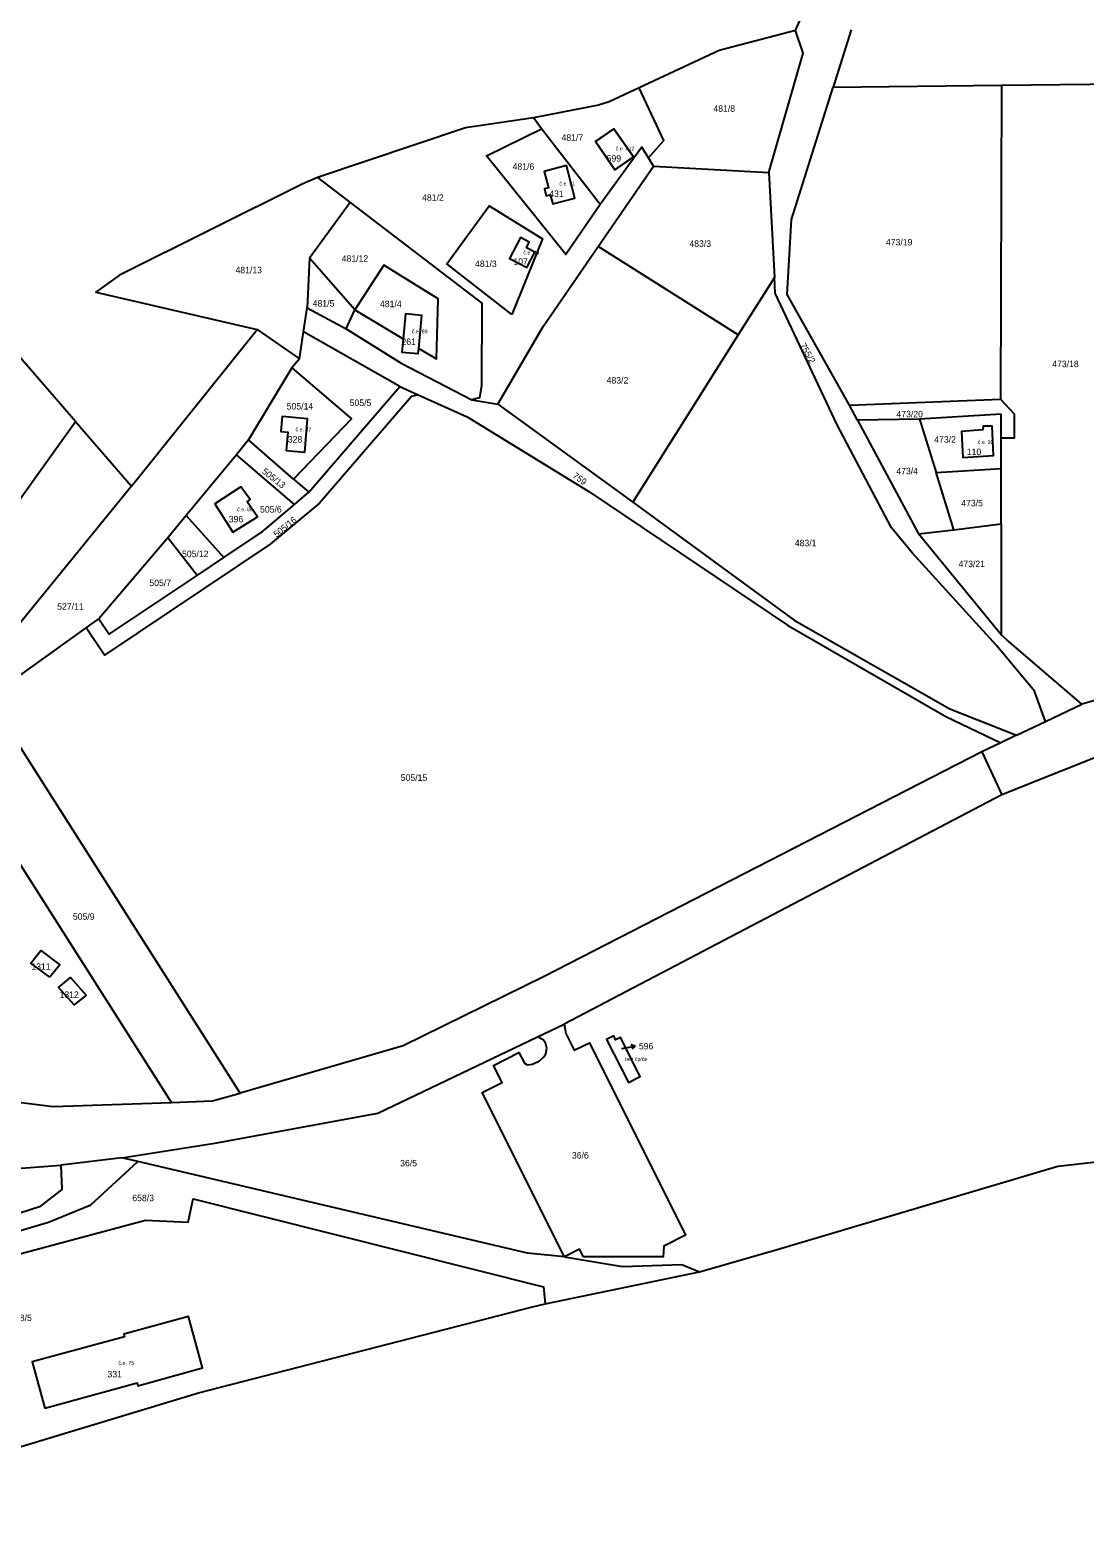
# Model space of a CAD drawing. Extents: x -887272 to -877616, y -1026687 to -1019819.
# Drawn here: x -883645.6 to -883368.4, y -1024159.5 to -1023763.3 of the extents above; entities that cross this region are included whole.
import ezdxf

# ---------------------------------------------------------------- set-up
doc = ezdxf.new("R2010")
doc.units = 0
for name, color, linetype in [('Definiční body', 7, 'Continuous'), ('Hranice parcel', 7, 'Continuous'), ('Parcelní čísla', 7, 'Continuous'), ('Polygon budovy', 7, 'Continuous'), ('Pop  PČ popisy', 7, 'Continuous')]:
    doc.layers.add(name, color=color, linetype=linetype)

msp = doc.modelspace()

# ---------------------------------------------------------------- linework, layer by layer
at = {"layer": 'Hranice parcel'}
for p, q in [((-883633.66, -1023866.14), (-883788.3, -1023688.23)), ((-883444.46, -1023763.44), (-883427.95, -1023725.46)), ((-883429.84, -1023763.22), (-883434.55, -1023778.27)), ((-883434.55, -1023778.27), (-883390.32, -1023777.79)), ((-883390.32, -1023777.79), (-883390.61, -1023860.31)), ((-883390.32, -1023777.79), (-883353.3, -1023777.4)), ((-883511.21, -1023789.27), (-883513.28, -1023786.33)), ((-883495.74, -1023809.17), (-883511.21, -1023789.27)), ((-883481.76, -1023799.1), (-883483.12, -1023796.92)), ((-883570.02, -1023802.03), (-883561.45, -1023808.59)), ((-883496.31, -1023820.22), (-883481.76, -1023799.1)), ((-883481.76, -1023799.1), (-883451.46, -1023800.74)), ((-883451.46, -1023800.74), (-883450.01, -1023828.34)), ((-883561.45, -1023808.59), (-883572.14, -1023823.24)), ((-883459.48, -1023843.4), (-883496.31, -1023820.22)), ((-883572.14, -1023823.24), (-883572.76, -1023836.34)), ((-883450.01, -1023828.34), (-883459.48, -1023843.4)), ((-883573.72, -1023842.6), (-883572.76, -1023836.34)), ((-883572.76, -1023836.34), (-883562.48, -1023841.78)), ((-883546.95, -1023837.89), (-883547.55, -1023844.48)), ((-883618.89, -1023883.14), (-883585.89, -1023842)), ((-883585.89, -1023842), (-883574.82, -1023849.7)), ((-883574.82, -1023849.7), (-883573.72, -1023842.6)), ((-883548.42, -1023856.97), (-883573.72, -1023842.6)), ((-883547.55, -1023844.48), (-883547.87, -1023847.97)), ((-883459.48, -1023843.4), (-883487.2, -1023887.41)), ((-883574.82, -1023849.7), (-883576.78, -1023852.03)), ((-883576.78, -1023852.03), (-883588.17, -1023871.03)), ((-883572.33, -1023884.75), (-883548.42, -1023856.97)), ((-883548.42, -1023856.97), (-883543.56, -1023859.14)), ((-883529.54, -1023860.45), (-883522.66, -1023861.64)), ((-883522.66, -1023861.64), (-883487.2, -1023887.41)), ((-883430.28, -1023861.87), (-883390.61, -1023860.31)), ((-883428.2, -1023865.83), (-883430.28, -1023861.87)), ((-883411.84, -1023865.52), (-883428.2, -1023865.83)), ((-883428.2, -1023865.83), (-883412.13, -1023895.71)), ((-883390.38, -1023864.26), (-883411.84, -1023865.52)), ((-883411.84, -1023865.52), (-883407.49, -1023879.6)), ((-883390.39, -1023870.51), (-883390.38, -1023864.26)), ((-883633.66, -1023866.14), (-883618.89, -1023883.14)), ((-883588.17, -1023871.03), (-883591.35, -1023874.89)), ((-883576.32, -1023881.3), (-883588.17, -1023871.03)), ((-883390.4, -1023878.54), (-883390.39, -1023870.51)), ((-883591.35, -1023874.89), (-883604.52, -1023890.86)), ((-883576.14, -1023887.99), (-883591.35, -1023874.89)), ((-883576.32, -1023881.3), (-883572.33, -1023884.75)), ((-883407.49, -1023879.6), (-883390.4, -1023878.54)), ((-883402.86, -1023894.6), (-883407.49, -1023879.6)), ((-883390.42, -1023893.04), (-883390.4, -1023878.54)), ((-883618.89, -1023883.14), (-883653, -1023925)), ((-883576.14, -1023887.99), (-883572.33, -1023884.75)), ((-883604.52, -1023890.86), (-883609.36, -1023896.72)), ((-883604.52, -1023890.86), (-883594.64, -1023901.88)), ((-883402.86, -1023894.6), (-883390.42, -1023893.04)), ((-883390.42, -1023893.04), (-883390.4, -1023922.22)), ((-883609.36, -1023896.72), (-883627.54, -1023918.05)), ((-883601.71, -1023906.6), (-883609.36, -1023896.72)), ((-883412.13, -1023895.71), (-883402.86, -1023894.6)), ((-883390.4, -1023922.22), (-883412.13, -1023895.71)), ((-883601.71, -1023906.6), (-883594.64, -1023901.88)), ((-883656.45, -1023938.75), (-883630.8, -1023920.38)), ((-883630.8, -1023920.38), (-883627.54, -1023918.05)), ((-883353.44, -1023936), (-883369.18, -1023940.44)), ((-883590.41, -1024042.65), (-883656.45, -1023938.75)), ((-883378.78, -1023945.02), (-883369.18, -1023940.44)), ((-883386.38, -1023948.64), (-883378.78, -1023945.02)), ((-883608.39, -1024045.1), (-883669.93, -1023948.4)), ((-883386.38, -1023948.64), (-883390.5, -1023950.62)), ((-883390.5, -1023950.62), (-883395.52, -1023952.98)), ((-883395.52, -1023952.98), (-883390.28, -1023964.24)), ((-883390.28, -1023964.24), (-883505.22, -1024024.55)), ((-883512.22, -1024027.85), (-883505.22, -1024024.55)), ((-883621.46, -1024059.64), (-883637.46, -1024061.6)), ((-883617.24, -1024060.68), (-883621.46, -1024059.64)), ((-883510.26, -1024098.08), (-883469.7, -1024089.6))]:
    msp.add_line(p, q, dxfattribs=at)
for points in [[(-883444.46, -1023763.44), (-883464.53, -1023768.66), (-883485.56, -1023778.53)], [(-883451.46, -1023800.74), (-883442.46, -1023769.38), (-883444.46, -1023763.44)], [(-883485.56, -1023778.53), (-883493.38, -1023782.2), (-883496.2, -1023783), (-883513.28, -1023786.33)], [(-883483.12, -1023796.92), (-883479.07, -1023792.34), (-883485.56, -1023778.53)], [(-883430.28, -1023861.87), (-883446.66, -1023832.78), (-883445.52, -1023813.08), (-883434.55, -1023778.27)], [(-883513.28, -1023786.33), (-883531.14, -1023788.98), (-883570.02, -1023802.03)], [(-883495.74, -1023809.17), (-883504.77, -1023822.27), (-883525.68, -1023796.36), (-883511.21, -1023789.27)], [(-883491.94, -1023800.04), (-883496.99, -1023792.63), (-883492.23, -1023789.26), (-883487.02, -1023796.59), (-883491.94, -1023800.04)], [(-883483.12, -1023796.92), (-883484.87, -1023794.12), (-883495.74, -1023809.17)], [(-883570.02, -1023802.03), (-883574.04, -1023803.84), (-883622.1, -1023827.7), (-883628.32, -1023832.18), (-883585.89, -1023842)], [(-883508.25, -1023808.95), (-883502.45, -1023807.49), (-883504.6, -1023798.93), (-883510.53, -1023800.47), (-883509.38, -1023804.74), (-883510.44, -1023805.02), (-883509.95, -1023806.87), (-883508.89, -1023806.58), (-883508.25, -1023808.95)], [(-883561.45, -1023808.59), (-883526.89, -1023835.05), (-883526.96, -1023856.69), (-883527.52, -1023859.93), (-883529.54, -1023860.45)], [(-883519.02, -1023838.04), (-883536.1, -1023824.78), (-883524.92, -1023809.52), (-883510.92, -1023818.14), (-883519.02, -1023838.04)], [(-883515.02, -1023825.7), (-883512.96, -1023821.7), (-883515.18, -1023820.56), (-883514.4, -1023819.04), (-883516.73, -1023817.86), (-883519.56, -1023823.37), (-883515.02, -1023825.7)], [(-883522.66, -1023861.64), (-883510.74, -1023841.18), (-883496.31, -1023820.22)], [(-883940.39, -1023824.94), (-883938.55, -1023836.46), (-883898.48, -1023883.66), (-883867.13, -1023900.11), (-883760.97, -1023903.17), (-883683.16, -1023912.16), (-883662.96, -1023907.05), (-883633.66, -1023866.14)], [(-883562.48, -1023841.78), (-883560.24, -1023836.86), (-883572.14, -1023823.24)], [(-883543.44, -1023846.95), (-883538.8, -1023849.74), (-883538.36, -1023833.9), (-883552.6, -1023825.06), (-883560.24, -1023836.86), (-883547.55, -1023844.48)], [(-883378.78, -1023945.02), (-883381.64, -1023937.06), (-883391.62, -1023925.06), (-883413.78, -1023900.7), (-883419.26, -1023894.08), (-883433.52, -1023867.02), (-883449.82, -1023832.42), (-883450.01, -1023828.34)], [(-883543.44, -1023846.95), (-883542.62, -1023838.3), (-883546.95, -1023837.89)], [(-883562.48, -1023841.78), (-883548.08, -1023850.86), (-883543.3, -1023853.3), (-883529.54, -1023860.45)], [(-883547.87, -1023847.97), (-883543.57, -1023848.32), (-883543.44, -1023846.95)], [(-883576.78, -1023852.03), (-883561.09, -1023865.51), (-883576.32, -1023881.3)], [(-883543.56, -1023859.14), (-883545.39, -1023859.58), (-883569.52, -1023887.62), (-883582.49, -1023898.39), (-883626.05, -1023927.56), (-883630.8, -1023920.38)], [(-883543.56, -1023859.14), (-883530.72, -1023864.92), (-883498.74, -1023884.54), (-883446.58, -1023919.7), (-883404.98, -1023943.72), (-883390.5, -1023950.62)], [(-883390.61, -1023860.31), (-883386.97, -1023864.2), (-883386.96, -1023870.52), (-883390.39, -1023870.51)], [(-883572.64, -1023865.46), (-883579.35, -1023864.88), (-883579.69, -1023868.84), (-883577.84, -1023869), (-883578.26, -1023873.81), (-883573.39, -1023874.23), (-883572.64, -1023865.46)], [(-883395.22, -1023868.36), (-883400.84, -1023868.84), (-883400.46, -1023875.62), (-883392.4, -1023875.08), (-883392.76, -1023867.36), (-883395.14, -1023867.44), (-883395.22, -1023868.36)], [(-883585.86, -1023891.24), (-883588.5, -1023887.26), (-883587.78, -1023886.7), (-883590.22, -1023883.32), (-883597, -1023887.8), (-883592.28, -1023895.26), (-883585.86, -1023891.24)], [(-883594.64, -1023901.88), (-883584.6, -1023895.17), (-883576.14, -1023887.99)], [(-883487.2, -1023887.41), (-883444.82, -1023918.42), (-883403.92, -1023941.64), (-883386.38, -1023948.64)], [(-883627.54, -1023918.05), (-883624.8, -1023922.02), (-883601.71, -1023906.6)], [(-883369.18, -1023940.44), (-883388.9, -1023923.52), (-883390.4, -1023922.22)], [(-883240.89, -1023944.68), (-883259.18, -1023943.04), (-883290.58, -1023940.7), (-883342.16, -1023945.12), (-883390.28, -1023964.24)], [(-883395.52, -1023952.98), (-883510.5, -1024012.06), (-883547.52, -1024030.26), (-883590.41, -1024042.65)], [(-883640.42, -1024012.24), (-883645.42, -1024008.51), (-883642.72, -1024005.16), (-883637.76, -1024008.92), (-883640.42, -1024012.24)], [(-883630.81, -1024016.94), (-883634.01, -1024019.51), (-883638.13, -1024014.92), (-883634.97, -1024012.27), (-883630.81, -1024016.94)], [(-883751.85, -1024024.16), (-883686.7, -1024040.32), (-883639.5, -1024046.16), (-883608.39, -1024045.1)], [(-883505.22, -1024024.55), (-883504.83, -1024026.96), (-883502.61, -1024031.4), (-883498.62, -1024029.42), (-883473.39, -1024079.97), (-883479.09, -1024082.85), (-883479.23, -1024085.66), (-883500.17, -1024085.66), (-883501.18, -1024083.64), (-883505.17, -1024085.66)], [(-883621.46, -1024059.64), (-883596.48, -1024055.74), (-883554.16, -1024047.98), (-883512.22, -1024027.85)], [(-883505.17, -1024085.66), (-883526.75, -1024042.51), (-883521.49, -1024039.88), (-883523.79, -1024035.45), (-883517.14, -1024032), (-883515.69, -1024034.77), (-883514.92, -1024035.2), (-883513.52, -1024035.04), (-883511.73, -1024034.15), (-883510.61, -1024033.16), (-883510.05, -1024032.34), (-883509.78, -1024030.88), (-883510.15, -1024029.44), (-883510.79, -1024028.68), (-883512.22, -1024027.85)], [(-883488.35, -1024039.92), (-883485.23, -1024038.34), (-883490.47, -1024028.01), (-883491.72, -1024028.64), (-883492.22, -1024027.65), (-883494.08, -1024028.6), (-883488.35, -1024039.92)], [(-883469.7, -1024089.6), (-883449.24, -1024083.76), (-883375.54, -1024061.88), (-883326.34, -1024056.38), (-883266.28, -1024028.21)], [(-883608.39, -1024045.1), (-883597.64, -1024044.74), (-883590.41, -1024042.65)], [(-883690.56, -1024054.21), (-883647.79, -1024062.38), (-883637.46, -1024061.6)], [(-883846.21, -1024144.12), (-883816.92, -1024155.06), (-883797.46, -1024159.1), (-883785.24, -1024159.54), (-883770.02, -1024156.86), (-883754.54, -1024149.76), (-883741.82, -1024138.86), (-883718.28, -1024114.56), (-883704.22, -1024101.36), (-883679.66, -1024088.08), (-883640.76, -1024076.54), (-883629.62, -1024072.06), (-883617.24, -1024060.68)], [(-883637.46, -1024061.6), (-883637.26, -1024068), (-883643.06, -1024072.58), (-883682.06, -1024085.08), (-883705.66, -1024098.02), (-883721, -1024111.1), (-883722.33, -1024112.53)], [(-883505.17, -1024085.66), (-883514.84, -1024084.74), (-883617.24, -1024060.68)], [(-883750.88, -1024152.74), (-883746.1, -1024149.26), (-883718.1, -1024121.38), (-883676.52, -1024093.5), (-883665.32, -1024089.44), (-883615.24, -1024076.02), (-883604.08, -1024076.62), (-883602.76, -1024070.42), (-883510.71, -1024093.58), (-883510.26, -1024098.08)], [(-883505.17, -1024085.66), (-883489.92, -1024088.22), (-883474.36, -1024087.72), (-883469.7, -1024089.6)], [(-883665.07, -1024140.74), (-883601.32, -1024121.4), (-883513.54, -1024098.82), (-883510.26, -1024098.08)], [(-883603.98, -1024101.37), (-883620.97, -1024106.03), (-883620.79, -1024106.69), (-883644.99, -1024113.32), (-883641.67, -1024125.43), (-883617.48, -1024118.8), (-883617.27, -1024119.56), (-883600.27, -1024114.9), (-883603.98, -1024101.37)]]:
    msp.add_lwpolyline(points, dxfattribs=at)
at = {"layer": 'Polygon budovy'}
for points in [[(-883492.23, -1023789.26), (-883496.99, -1023792.63), (-883491.94, -1023800.04), (-883487.02, -1023796.59)], [(-883504.6, -1023798.93), (-883510.53, -1023800.47), (-883509.38, -1023804.74), (-883510.44, -1023805.02), (-883509.95, -1023806.87), (-883508.89, -1023806.58), (-883508.25, -1023808.95), (-883502.45, -1023807.49)], [(-883519.56, -1023823.37), (-883515.02, -1023825.7), (-883512.96, -1023821.7), (-883515.18, -1023820.56), (-883514.4, -1023819.04), (-883516.73, -1023817.86)], [(-883542.62, -1023838.3), (-883546.95, -1023837.89), (-883547.55, -1023844.48), (-883547.87, -1023847.97), (-883543.57, -1023848.32), (-883543.44, -1023846.95)], [(-883579.35, -1023864.88), (-883579.69, -1023868.84), (-883577.84, -1023869), (-883578.26, -1023873.81), (-883573.39, -1023874.23), (-883572.64, -1023865.46)], [(-883400.46, -1023875.62), (-883392.4, -1023875.08), (-883392.76, -1023867.36), (-883395.14, -1023867.44), (-883395.22, -1023868.36), (-883400.84, -1023868.84)], [(-883597, -1023887.8), (-883592.28, -1023895.26), (-883585.86, -1023891.24), (-883588.5, -1023887.26), (-883587.78, -1023886.7), (-883590.22, -1023883.32)], [(-883492.22, -1024027.65), (-883494.08, -1024028.6), (-883488.35, -1024039.92), (-883485.23, -1024038.34), (-883490.47, -1024028.01), (-883491.72, -1024028.64)], [(-883641.67, -1024125.43), (-883617.48, -1024118.8), (-883617.27, -1024119.56), (-883600.27, -1024114.9), (-883603.98, -1024101.37), (-883620.97, -1024106.03), (-883620.79, -1024106.69), (-883644.99, -1024113.32)]]:
    msp.add_lwpolyline(points, close=True, dxfattribs=at)
at = {"layer": 'Pop  PČ popisy'}
for p, q in [((-883490.14, -1024030.95), (-883489.56, -1024030.85)), ((-883489.56, -1024030.85), (-883486.6, -1024030.33)), ((-883486.6, -1024030.33), (-883487.68, -1024030.01)), ((-883486.6, -1024030.33), (-883487.5, -1024031))]:
    msp.add_line(p, q, dxfattribs=at)

# ---------------------------------------------------------------- texts
at = {"layer": 'Definiční body'}
for s, p in [('č.e. 412', (-883491.7, -1023794.93)), ('č.e. 91', (-883506.49, -1023804.15)), ('č.e. 90', (-883515.95, -1023822.28)), ('č.e. 89', (-883545.27, -1023842.99)), ('č.e. 87', (-883575.82, -1023868.76)), ('č.e. 92', (-883396.55, -1023872.04)), ('č.e. 86', (-883591.15, -1023889.74)), ('bez čp/če', (-883489.27, -1024034.22)), ('č.e. 75', (-883622.38, -1024114.08))]:
    msp.add_text(s, height=1, dxfattribs=at).set_placement(p)
at = {"layer": 'Parcelní čísla'}
for s, p in [('481/8', (-883466.02, -1023784.79)), ('481/7', (-883505.94, -1023792.41)), ('481/6', (-883518.79, -1023800.01)), ('599', (-883494.07, -1023797.89)), ('481/2', (-883542.57, -1023808.16)), ('431', (-883509.16, -1023807.17)), ('483/3', (-883472.33, -1023820.28)), ('473/19', (-883420.69, -1023819.9)), ('481/12', (-883563.69, -1023824.19)), ('481/13', (-883591.6, -1023827.22)), ('481/3', (-883528.65, -1023825.58)), ('107', (-883518.58, -1023824.98)), ('481/5', (-883571.32, -1023835.98)), ('481/4', (-883553.63, -1023836.13)), ('261', (-883547.99, -1023846.06)), ('473/18', (-883376.99, -1023851.89)), ('483/2', (-883494.08, -1023856.19)), ('505/14', (-883578.14, -1023863.02)), ('505/5', (-883561.59, -1023862.09)), ('473/20', (-883417.93, -1023865.08)), ('328', (-883577.86, -1023871.72)), ('473/2', (-883407.99, -1023871.74)), ('110', (-883399.44, -1023874.99)), ('473/4', (-883417.96, -1023880.05)), ('505/6', (-883585.15, -1023890.11)), ('473/5', (-883400.9, -1023888.46)), ('396', (-883593.36, -1023892.68)), ('483/1', (-883444.64, -1023898.96)), ('505/12', (-883605.65, -1023901.82)), ('473/21', (-883401.61, -1023904.44)), ('505/7', (-883614.23, -1023909.44)), ('527/11', (-883638.45, -1023915.64)), ('505/15', (-883548.17, -1023960.61)), ('505/9', (-883634.33, -1023997.12)), ('1311', (-883645.24, -1024010.27)), ('1312', (-883637.83, -1024017.64)), ('596', (-883485.61, -1024031.17)), ('36/5', (-883548.33, -1024061.92)), ('36/6', (-883503.2, -1024059.87)), ('658/3', (-883618.71, -1024071.07)), ('658/5', (-883650.81, -1024102.58)), ('331', (-883625.24, -1024117.37))]:
    msp.add_text(s, height=1.7, dxfattribs=at).set_placement(p)
for s, rotation, p in [('755/2', 299, (-883443.38, -1023846.13)), ('505/13', 322, (-883584.81, -1023879.6)), ('759', 324, (-883503.17, -1023880.79)), ('505/16', 39, (-883580.76, -1023896.74))]:
    msp.add_text(s, height=1.7, rotation=rotation, dxfattribs=at).set_placement(p)

doc.saveas('drawing.dxf')
